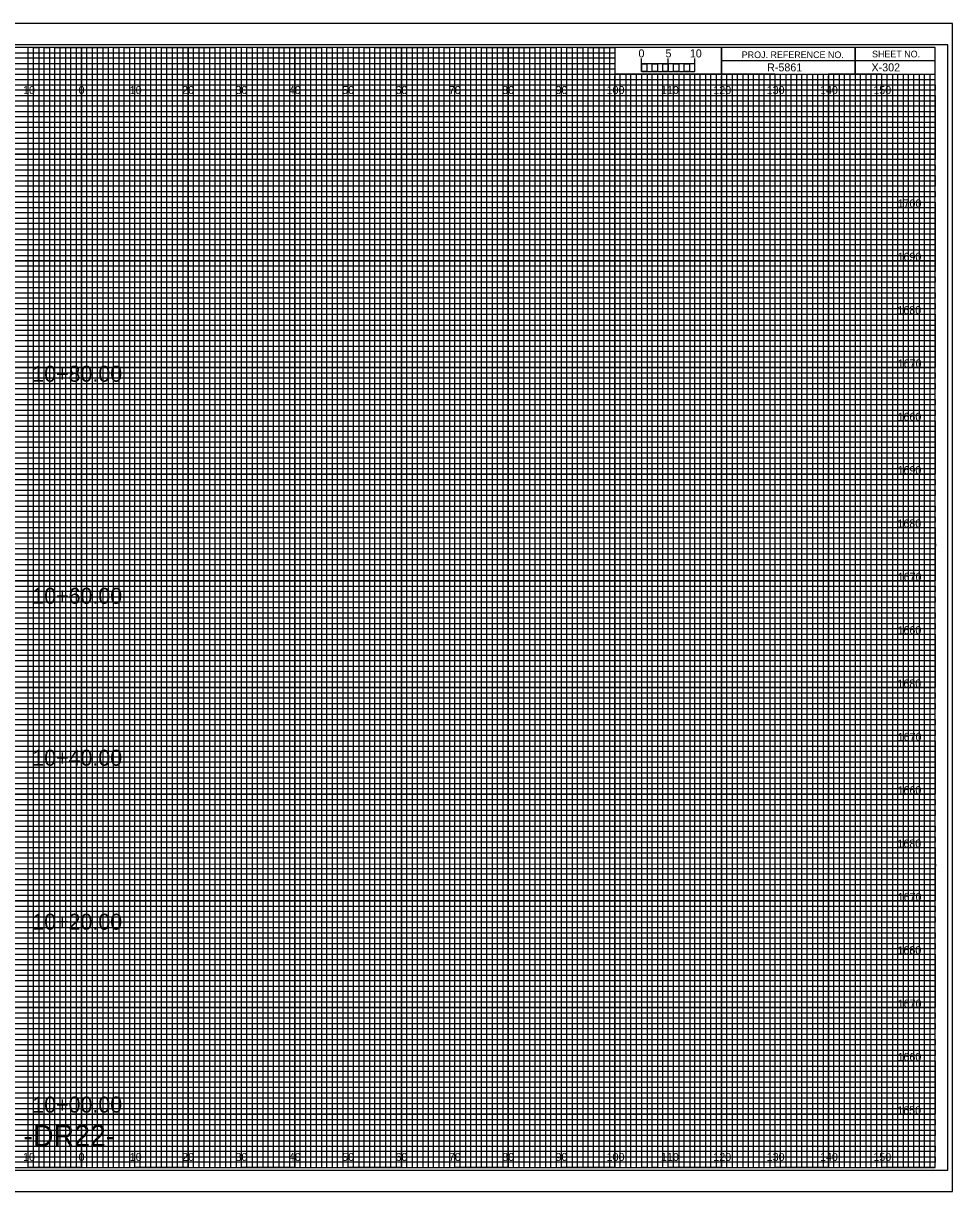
# Model space of a CAD drawing. Extents: x -13 to 323, y -5 to 434.
# Drawn here: x 149.1 to 323.3, y -4.5 to 214.5 of the extents above; entities that cross this region are included whole.
import ezdxf

# ---------------------------------------------------------------- set-up
doc = ezdxf.new("R2010")
doc.units = 0
for name, color, linetype in [('Prop Horizontal Alignment', 7, 'Continuous'), ('Prop XS Alignment Label', 7, 'Continuous'), ('Prop XS Bar Scale Labels', 7, 'Continuous'), ('Prop XS Project Number', 7, 'Continuous'), ('Prop XS Sheet Number', 7, 'Continuous'), ('Raster_Level_0', 7, 'Continuous'), ('Scratch_Level_3', 7, 'Continuous'), ('Sheet Cross Section CELL', 7, 'Continuous'), ('Sheet Cross Section Grid Major CELL', 7, 'Continuous'), ('Sheet Cross Section Grid Middle CELL', 7, 'Continuous'), ('Sheet Cross Section Grid Minor 1 CELL', 7, 'Continuous'), ('Sheet Cross Section Grid Minor 2 CELL', 7, 'Continuous'), ('Sheet Cross Section Scale CELL', 7, 'Continuous'), ('Sheet Cutting Line CELL', 7, 'Continuous'), ('Sheet DOT Grid CELL', 7, 'Continuous'), ('Sheet Plot Border Inside CELL', 7, 'Continuous'), ('Sheet Plot Border Outside CELL', 7, 'Continuous')]:
    doc.layers.add(name, color=color, linetype=linetype)

msp = doc.modelspace()

# ---------------------------------------------------------------- linework, layer by layer
at = {"layer": 'Sheet Cross Section CELL'}
for p, q in [((305, 210), (305, 205)), ((305, 205), (305, 210)), ((280, 207.5), (280, 205)), ((320, 207.49), (280, 207.49)), ((280, 205), (320, 205))]:
    msp.add_line(p, q, dxfattribs=at)
for points in [[(320, 210), (0, 210), (0, 0), (320, 0)], [(280, 210), (260, 210), (260, 205.03), (280, 205.03)], [(320, 210), (280, 210), (280, 205), (320, 205)]]:
    msp.add_lwpolyline(points, close=True, dxfattribs=at)
at = {"layer": 'Sheet Cross Section Grid Major CELL'}
for p, q in [((150, 210), (140, 210)), ((150, 0), (150, 210)), ((170, 210), (160, 210)), ((160, 210), (160, 0)), ((170, 0), (170, 210)), ((190, 210), (180, 210)), ((180, 210), (180, 0)), ((190, 0), (190, 210)), ((210, 210), (200, 210)), ((200, 210), (200, 0)), ((210, 0), (210, 210)), ((230, 210), (220, 210)), ((220, 210), (220, 0)), ((230, 0), (230, 210)), ((250, 210), (240, 210)), ((240, 210), (240, 0)), ((250, 0), (250, 210)), ((260, 210), (260, 0)), ((270, 0), (270, 205)), ((290, 205), (280, 205)), ((280, 205), (280, 0)), ((290, 0), (290, 205)), ((310, 205), (300, 205)), ((300, 205), (300, 0)), ((310, 0), (310, 205)), ((160, 0), (150, 0)), ((180, 0), (170, 0)), ((200, 0), (190, 0)), ((220, 0), (210, 0)), ((240, 0), (230, 0)), ((260, 0), (250, 0)), ((280, 0), (270, 0)), ((300, 0), (290, 0)), ((320, 0), (310, 0)), ((320, 0), (320, 0))]:
    msp.add_line(p, q, dxfattribs=at)
for points in [[(0, 200), (320, 200), (320, 190), (0, 190)], [(0, 180), (320, 180), (320, 170), (0, 170)], [(0, 160), (320, 160), (320, 150), (0, 150)], [(0, 140), (320, 140), (320, 130), (0, 130)], [(0, 120), (320, 120), (320, 110), (0, 110)], [(0, 100), (320, 100), (320, 90), (0, 90)], [(0, 80), (320, 80), (320, 70), (0, 70)], [(0, 60), (320, 60), (320, 50), (0, 50)], [(0, 40), (320, 40), (320, 30), (0, 30)], [(0, 20), (320, 20), (320, 10), (0, 10)]]:
    msp.add_lwpolyline(points, dxfattribs=at)
at = {"layer": 'Sheet Cross Section Grid Middle CELL'}
for points in [[(145, 0), (155, 0), (155, 210), (165, 210), (165, 0), (175, 0), (175, 210), (185, 210), (185, 0), (195, 0), (195, 210), (205, 210), (205, 0), (215, 0), (215, 210), (225, 210), (225, 0), (235, 0), (235, 210), (245, 210), (245, 0), (255, 0), (255, 210), (259.93, 210), (260, 210), (260, 205), (264.99, 205), (264.99, 0), (275, 0), (275, 205), (285, 205), (285, 0), (295, 0), (295, 205), (305, 205), (305, 0), (315, 0), (315, 205)], [(0, 205), (275, 205)], [(0, 185), (320, 185), (320, 195), (0, 195)], [(0, 165), (320, 165), (320, 175), (0, 175)], [(0, 145), (320, 145), (320, 155), (0, 155)], [(0, 125), (320, 125), (320, 135), (0, 135)], [(0, 105), (320, 105), (320, 115), (0, 115)], [(0, 85), (320, 85), (320, 95), (0, 95)], [(0, 65), (320, 65), (320, 75), (0, 75)], [(0, 45), (320, 45), (320, 55), (0, 55)], [(0, 25), (320, 25), (320, 35), (0, 35)], [(0, 5), (320, 5), (320, 15), (0, 15)]]:
    msp.add_lwpolyline(points, dxfattribs=at)
at = {"layer": 'Sheet Cross Section Grid Minor 1 CELL'}
for p, q in [((0, 209), (260, 209)), ((260, 209), (260, 207.98)), ((260, 207.98), (0, 207.98)), ((0, 207), (260, 207)), ((260, 205.89), (0, 205.89)), ((260, 207), (260, 205.89)), ((0, 204), (320, 204))]:
    msp.add_line(p, q, dxfattribs=at)
for points in [[(0, 203), (270, 203), (320, 203), (320, 202), (0, 202)], [(0, 201), (320, 201), (320, 199), (0, 199)], [(0, 198), (320, 198), (320, 197), (0, 196.98)], [(0, 196), (320, 196), (320, 194), (0, 194)], [(0, 193), (320, 193), (320, 192), (0, 192)], [(0, 191), (320, 191), (320, 189), (0, 189)], [(0, 188), (320, 188), (320, 187), (0, 187)], [(0, 186), (320, 186), (320, 184), (0, 184)], [(0, 183), (320, 183), (320, 182), (0, 182)], [(0, 181), (320, 181), (320, 179), (0, 179)], [(0, 178), (320, 178), (320, 177), (0, 177)], [(0, 176), (320, 176), (320, 173.95), (320, 173), (320, 172), (0, 172)], [(0, 174), (320, 174), (320, 173), (0, 173)], [(0, 171), (320, 171), (320, 169), (0, 169.03)], [(0, 169.03), (320, 169), (320, 168), (0, 168)], [(0, 167), (320, 167), (320, 166), (0, 166)], [(0, 164), (320, 164), (320, 163), (0, 163)], [(0, 162), (320, 162), (320, 161), (0, 161)], [(-0.07, 158.89), (320, 158.89), (320, 157.88), (-0.07, 157.88)], [(0, 157), (320, 157), (320, 156), (0, 156)], [(0, 154), (320, 154), (320, 153), (0, 153)], [(0, 152), (320, 152), (320, 151), (0, 151)], [(0, 149), (320, 149), (320, 148), (0, 148)], [(0, 147), (320, 147), (320, 146), (0, 146)], [(0, 144), (320, 144), (320, 143), (0, 143)], [(0, 142), (320, 142), (320, 141), (0, 141)], [(0, 139), (320, 139), (319.99, 137.98), (0, 138)], [(0, 137), (320, 137), (320, 136), (0, 136)], [(0, 134), (320, 134), (320, 133), (0, 133)], [(0, 132), (320, 132), (320, 131), (0, 131)], [(0, 129), (320, 129), (320, 128), (0, 128)], [(0, 127), (320, 127), (320, 126), (0, 126)], [(0, 124), (320, 124), (320, 123), (0, 123)], [(0, 122), (320, 122), (320, 121), (0, 121)], [(0, 119), (320, 119), (320, 118), (0, 118)], [(0, 116.99), (320.07, 116.91), (320, 116), (0, 116)], [(0, 114), (320, 114), (320, 113), (0, 113)], [(0, 112), (320, 112), (320, 111), (0, 111)], [(0, 109), (320, 109), (320, 108), (0, 108)], [(0, 107), (320, 107), (320, 106), (0, 106)], [(0, 104), (320, 104), (320, 103), (0, 103)], [(0, 102), (320, 102), (320, 101), (0, 101)], [(0, 99), (320, 99), (320, 98), (0, 98)], [(0, 97), (320, 97), (320, 96), (0, 96)], [(0, 94), (320, 94), (320, 93), (0, 93)], [(0, 92), (320, 92), (320, 91), (0, 91)], [(0, 89), (320, 89), (320, 88), (0, 88)], [(0, 87), (320, 87), (320, 86), (0, 86)], [(0, 84), (320, 84), (320, 83), (0, 83)], [(0, 82), (320, 82), (320, 81), (0, 81)], [(0, 79), (320, 79), (319.99, 77.98), (0, 78)], [(0, 77), (320, 77), (320, 76), (0, 76)], [(0, 74), (320, 74), (320, 73), (0, 73)], [(0, 72), (320, 72), (320, 71), (0, 71)], [(0, 69), (320, 69), (320, 68), (0, 68)], [(0, 67), (320, 67), (320, 66), (0, 66)], [(0, 64), (320, 64), (320, 63), (0, 63)], [(0, 62), (320, 62), (320, 61), (0, 61)], [(0, 59), (320, 59), (320, 58), (0, 58)], [(0, 56.99), (320.07, 56.91), (320, 56), (0, 56)], [(0, 54), (320, 54), (320, 53), (0, 53)], [(0, 52), (320, 52), (320, 51), (0, 51)], [(0, 49), (320, 49), (320, 48), (0, 48)], [(0, 47), (320, 47), (320, 46), (0, 46)], [(0, 44), (320, 44), (320, 43), (0, 43)], [(0, 42), (320, 42), (320, 41), (0, 41)], [(0, 39), (320, 39), (320, 38), (0, 38)], [(0, 37), (320, 37), (320, 36), (0, 36)], [(0, 34), (320, 34), (320, 33), (0, 33)], [(0, 32), (320, 32), (320, 31), (0, 31)], [(0, 29), (320, 29), (320, 28), (0, 28)], [(0, 27), (320, 27), (320, 26), (0, 26)], [(0, 24), (320, 24), (320, 23), (0, 23)], [(0, 22), (320, 22), (320, 21), (0, 21)], [(0, 19), (320, 19), (320, 18), (0, 18)], [(0, 17), (320, 17), (320, 16), (0, 16)], [(0, 14), (320, 14), (320, 13), (0, 13)], [(0, 12), (320, 12), (320, 11), (0, 11)], [(0, 9), (320, 9), (320, 8), (0, 8)], [(0, 7), (320, 7), (320, 6), (0, 6)], [(0, 4), (320, 4), (320, 3), (0, 3)], [(0, 2), (320, 2), (320, 1), (0, 1)]]:
    msp.add_lwpolyline(points, dxfattribs=at)
at = {"layer": 'Sheet Cross Section Grid Minor 2 CELL'}
for p, q in [((267, 205), (266.01, 205)), ((266.01, 205), (266.01, 0)), ((267, 0), (267, 205)), ((269, 205), (268, 205)), ((268, 205), (268, 0)), ((269, 0), (269, 205)), ((266.01, 0), (265, 0)), ((268, 0), (267, 0))]:
    msp.add_line(p, q, dxfattribs=at)
for points in [[(150, 0), (151, 0), (151, 210), (152, 210), (152, 0)], [(152, 0), (153, 0), (153, 210), (154, 210), (154, 0)], [(155, 0), (156, 0), (156, 210), (157, 210), (157, 0)], [(157, 0), (158, 0), (158, 210), (159, 210), (159, 0)], [(160, 0), (161, 0), (161, 210), (162, 210), (162, 0)], [(162, 0), (163, 0), (163, 210), (164, 210), (164, 0)], [(165, 0), (166, 0), (166, 210), (167, 210), (167, 0)], [(167, 0), (168, 0), (168, 210), (169, 210), (169, 0)], [(170, 0), (171, 0), (171, 210), (172, 210), (172, 0)], [(172, 0), (173, 0), (173, 210), (174, 210), (174, 0)], [(175, 0), (176, 0), (176, 210), (177, 210), (177, 0)], [(177, 0), (178, 0), (178, 210), (179, 210), (179, 0)], [(180, 0), (181, 0), (181, 210), (182, 210), (182, 0)], [(182, 0), (183, 0), (183, 210), (184, 210), (184, 0)], [(185, 0), (186, 0), (186, 210), (187, 210), (187, 0)], [(187, 0), (188, 0), (188, 210), (189, 210), (189, 0)], [(190, 0), (191, 0), (191, 210), (192, 210), (192, 0)], [(192, 0), (193, 0), (193, 210), (194, 210), (194, 0)], [(195, 0), (196, 0), (196, 210), (197, 210), (197, 0)], [(197, 0), (198, 0), (198, 210), (199, 210), (199, 0)], [(200, 0), (201, 0), (201, 210), (202, 210), (202, 0)], [(202, 0), (203, 0), (203, 210), (204, 210), (204, 0)], [(205, 0), (206, 0), (206, 210), (207, 210), (207, 0)], [(207, 0), (208, 0), (208, 210), (209, 210), (209, 0)], [(210, 0), (211, 0), (211, 210), (212, 210), (212, 0)], [(212, 0), (213, 0), (213, 210), (214, 210), (214, 0)], [(215, 0), (216, 0), (216, 210), (217, 210), (217, 0)], [(217, 0), (218, 0), (218, 210), (219, 210), (219, 0)], [(220, 0), (221, 0), (221, 210), (222, 210), (222, 0)], [(222, 0), (223, 0), (223, 210), (224, 210), (224, 0)], [(225, 0), (226, 0), (226, 210), (227, 210), (227, 0)], [(227, 0), (228, 0), (228, 210), (229, 210), (229, 0)], [(230, 0), (231, 0), (231, 210), (232, 210), (232, 0)], [(232, 0), (233, 0), (233, 210), (234, 210), (234, 0)], [(235, 0), (236, 0), (236, 210), (237, 210), (237, 0)], [(237, 0), (238, 0), (238, 210), (239, 210), (239, 0)], [(240, 0), (241, 0), (241, 210), (242, 210), (242, 0)], [(242, 0), (243, 0), (243, 210), (244, 210), (244, 0)], [(245, 0), (246, 0), (246, 210), (247, 210), (247, 0)], [(247, 0), (248, 0), (248, 210), (249, 210), (249, 0)], [(250, 0), (251, 0), (251, 210), (252, 210), (252, 0)], [(252, 0), (253, 0), (253, 210), (254, 210), (254, 0)], [(255, 0), (256, 0), (256, 210), (257, 210), (257, 0)], [(257, 0), (258, 0), (258, 210), (259, 210), (259, 0)], [(260, 0), (261, 0), (261, 205), (262.02, 205), (262.02, 0)], [(262, 0), (263, 0), (263, 205), (263.99, 205), (263.99, 0)], [(270, 0), (270.98, 0), (270.98, 205), (272, 205), (272, 0)], [(272, 0), (273, 0), (273, 205), (274.05, 205), (274.05, 0)], [(275, 0), (276, 0), (276, 205), (277, 205), (277, 0)], [(277, 0), (278, 0), (278, 205), (279, 205), (279, 0)], [(280, 0), (281, 0), (281, 205), (282, 205), (282, 0)], [(282, 0), (283, 0), (283, 205), (284, 205), (284, 0)], [(285, 0), (286, 0), (286, 205), (287, 205), (287, 0)], [(287, 0), (288, 0), (288, 205), (289, 205), (289, 0)], [(290, 0), (291, 0), (291, 205), (292, 205), (292, 0)], [(292, 0), (293, 0), (293, 205), (294, 205), (294, 0)], [(295, 0), (296, 0), (296, 205), (297, 205), (297, 0)], [(297, 0), (298, 0), (298, 205), (299, 205), (299, 0)], [(300, 0), (301, 0), (301, 205), (302, 205), (302, 0)], [(302, 0), (303, 0), (303, 205), (304, 205), (304, 0)], [(305, 0), (306, 0), (306, 205), (307, 205), (307, 0)], [(307, 0), (308, 0), (308, 205), (309, 205), (309, 0)], [(310, 0), (311, 0), (311, 205), (312, 205), (312, 0)], [(312, 0), (313, 0), (313, 205), (314, 205), (314, 0)], [(315, 0), (316, 0), (316, 205), (317, 205), (317, 0)], [(317, 0), (318, 0), (318, 205), (319, 205), (319, 0)]]:
    msp.add_lwpolyline(points, dxfattribs=at)
at = {"layer": 'Sheet Cross Section Scale CELL'}
for p, q in [((265, 205.49), (265, 207.9)), ((265, 206.9), (265, 207.9)), ((270, 205.49), (270, 207.9)), ((275, 205.49), (275, 207.9)), ((275, 206.9), (275, 207.9))]:
    msp.add_line(p, q, dxfattribs=at)
for points in [[(275, 206.9), (265, 206.9), (265, 205.49), (275, 205.49)], [(265, 206.9), (266, 206.9), (266, 205.49), (265, 205.49)], [(267, 206.9), (268, 206.9), (268, 205.49), (267, 205.49)], [(269, 206.9), (270, 206.9), (270, 205.49), (269, 205.49)], [(271, 206.9), (272, 206.9), (272, 205.49), (271, 205.49)], [(273, 206.9), (274, 206.9), (274, 205.49), (273, 205.49)]]:
    msp.add_lwpolyline(points, close=True, dxfattribs=at)
at = {"layer": 'Sheet Cutting Line CELL'}
for p, q in [((323.3, 214.5), (-13.4, 214.5)), ((-13.4, -4.5), (323.3, -4.5))]:
    msp.add_line(p, q, dxfattribs=at)
at = {"layer": 'Sheet DOT Grid CELL'}
for p, q in [((150, 0), (150, 210)), ((160, 0), (160, 210)), ((170, 0), (170, 210)), ((180, 0), (180, 210)), ((190, 0), (190, 210)), ((200, 0), (200, 210)), ((210, 0), (210, 210)), ((220, 0), (220, 210)), ((230, 0), (230, 210)), ((240, 0), (240, 210)), ((250, 0), (250, 210)), ((260, 0), (260, 204.69)), ((270, 0), (270, 204.69)), ((280, 0), (280, 204.69)), ((290, 0), (290, 204.69)), ((300, 0), (300, 204.69)), ((310, 0), (310, 204.69)), ((0, 200), (320, 200)), ((0, 190), (320, 190)), ((0, 180), (320, 180)), ((0, 170), (320, 170)), ((0, 160), (320, 160)), ((0, 150), (320, 150)), ((0, 140), (320, 140)), ((0, 130), (320, 130)), ((0, 120), (320, 120)), ((0, 110), (320, 110)), ((0, 100), (320, 100)), ((0, 90), (320, 90)), ((0, 80), (320, 80)), ((0, 70), (320, 70)), ((0, 60), (320, 60)), ((0, 50), (320, 50)), ((0, 40), (320, 40)), ((0, 30), (320, 30)), ((0, 20), (320, 20)), ((0, 10), (320, 10))]:
    msp.add_line(p, q, dxfattribs=at)
at = {"layer": 'Sheet Plot Border Inside CELL'}
msp.add_lwpolyline([(-10.8, -0.5), (322.4, -0.5), (322.4, 210.5), (-10.8, 210.5)], close=True, dxfattribs=at)
at = {"layer": 'Sheet Plot Border Outside CELL'}
msp.add_lwpolyline([(-13.4, -4.5), (323.3, -4.5), (323.3, 214.5), (-13.4, 214.5)], close=True, dxfattribs=at)

# ---------------------------------------------------------------- texts
at = {"layer": 'Prop Horizontal Alignment'}
for s, p in [('1700', (312.98, 180)), ('1690', (312.97, 170)), ('1680', (312.95, 160)), ('1670', (313, 150)), ('1660', (312.97, 140)), ('1690', (312.97, 130)), ('1680', (312.95, 120)), ('1670', (313, 110)), ('1660', (312.97, 100)), ('1680', (312.95, 90)), ('1670', (313, 80)), ('1660', (312.97, 70)), ('1680', (312.95, 60)), ('1670', (313, 50)), ('1680', (312.95, 40)), ('1660', (312.97, 40)), ('1670', (313, 30)), ('1660', (312.97, 20)), ('1650', (312.92, 10))]:
    msp.add_text(s, height=1.5, dxfattribs=at).set_placement(p)
at = {"layer": 'Prop XS Alignment Label'}
msp.add_text('-DR22-', height=4, dxfattribs=at).set_placement((149.11, 4))
at = {"layer": 'Prop XS Bar Scale Labels'}
for s, p in [('5', (269.47, 208.12)), ('10', (274.04, 208.12))]:
    msp.add_text(s, height=1.5, dxfattribs=at).set_placement(p)
at = {"layer": 'Prop XS Project Number'}
msp.add_text('R-5861', height=1.5, dxfattribs=at).set_placement((288.53, 205.5))
at = {"layer": 'Prop XS Sheet Number'}
msp.add_text('X-302', height=1.5, dxfattribs=at).set_placement((308.09, 205.5))
at = {"layer": 'Raster_Level_0'}
for s, p in [('10', (149.04, 201.25)), ('0', (159.45, 201.25)), ('0', (159.45, 201.25)), ('10', (169.04, 201.25)), ('20', (178.86, 201.25)), ('30', (188.86, 201.25)), ('40', (198.86, 201.25)), ('50', (208.86, 201.25)), ('60', (218.86, 201.25)), ('70', (228.86, 201.25)), ('80', (238.86, 201.25)), ('90', (248.86, 201.25)), ('100', (258.44, 201.25)), ('110', (268.62, 201.25)), ('120', (278.44, 201.25)), ('130', (288.44, 201.25)), ('140', (298.44, 201.25)), ('150', (308.44, 201.25)), ('10', (149.04, 1.25)), ('0', (159.45, 1.25)), ('0', (159.45, 1.25)), ('10', (169.04, 1.25)), ('20', (178.86, 1.25)), ('30', (188.86, 1.25)), ('40', (198.86, 1.25)), ('50', (208.86, 1.25)), ('60', (218.86, 1.25)), ('70', (228.86, 1.25)), ('80', (238.86, 1.25)), ('90', (248.86, 1.25)), ('100', (258.44, 1.25)), ('110', (268.62, 1.25)), ('120', (278.44, 1.25)), ('130', (288.44, 1.25)), ('140', (298.44, 1.25)), ('150', (308.44, 1.25))]:
    msp.add_text(s, height=1.5, dxfattribs=at).set_placement(p)
at = {"layer": 'Scratch_Level_3'}
for s, p in [('10+80.00', (150.77, 147.32)), ('10+60.00', (150.77, 105.7)), ('10+40.00', (150.77, 75.34)), ('10+20.00', (150.77, 44.6)), ('10+00.00', (150.77, 10.31))]:
    msp.add_text(s, height=3, dxfattribs=at).set_placement(p)
at = {"layer": 'Sheet Cross Section CELL'}
for s, p in [('PROJ. REFERENCE NO.', (283.77, 207.99)), ('SHEET NO.', (308.19, 208.12))]:
    msp.add_text(s, height=1.25, dxfattribs=at).set_placement(p)
at = {"layer": 'Sheet Cross Section Scale CELL'}
msp.add_text('0', height=1.5, dxfattribs=at).set_placement((264.41, 208.12))

doc.saveas('drawing.dxf')
